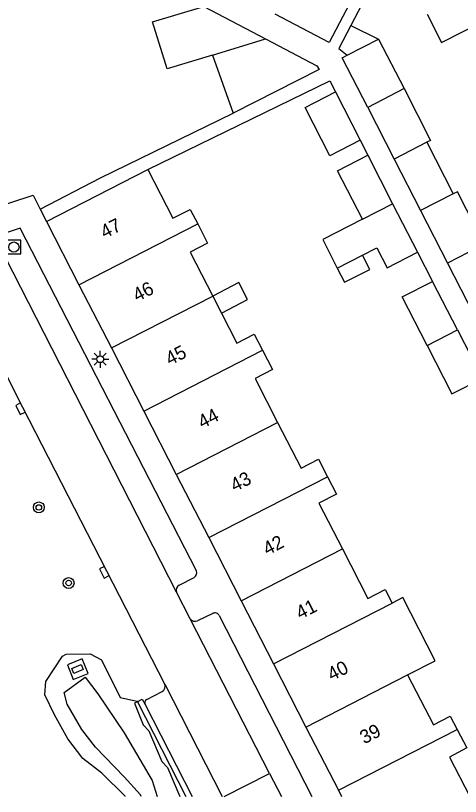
# Model space of a CAD drawing. Extents: x 132999 to 136000, y 398499 to 400501.
# Drawn here: x 133414.1 to 133446.8, y 398500 to 398557.3 of the extents above; entities that cross this region are included whole.
import ezdxf

# ---------------------------------------------------------------- set-up
doc = ezdxf.new("R2010")
doc.units = 0
for name, color, linetype in [('gg-afsc-erfafscheiding', 7, 'Continuous'), ('gg-anno-huisnummerreeks BGT', 7, 'Continuous'), ('gg-bbg-gedigitaliseerde bebouwing', 7, 'Continuous'), ('gg-bbg-gedigitaliseerde bijgebouw', 7, 'Continuous'), ('gg-bbg-hoofdgebouw', 7, 'Continuous'), ('gg-bbg-luifel en loopbrug', 7, 'Continuous'), ('gg-bbg-tussenscheiding', 7, 'Continuous'), ('gg-knt-verharding', 7, 'Continuous'), ('gg-knt-verharding nz', 7, 'Continuous'), ('gg-kntw-bovenkant insteek waterloop', 7, 'Continuous'), ('gg-kntw-waterlijn', 7, 'Continuous'), ('gt-grn-weggrens', 7, 'Continuous'), ('gt-symb-boom', 7, 'Continuous'), ('gt-symb-kolk', 7, 'Continuous'), ('gt-symb-kolk center center', 7, 'Continuous'), ('gt-symb-lichtmast', 7, 'Continuous'), ('gt-symb-rioolschacht', 7, 'Continuous')]:
    doc.layers.add(name, color=color, linetype=linetype)

# ---------------------------------------------------------------- blocks, each defined once
blk = doc.blocks.new('gt0-RS')
at = {"layer": 'gt-symb-rioolschacht'}
blk.add_lwpolyline([(-0.5, -0.5), (0.5, -0.5), (0.5, 0.5), (-0.5, 0.5)], close=True, dxfattribs=at)
blk.add_circle((0, 0), 0.375, dxfattribs=at)
blk = doc.blocks.new('gt0-KOLK')
at = {"layer": 'gt-symb-kolk'}
blk.add_lwpolyline([(0, 0), (0.375, 0), (0.375, 0.4), (-0.375, 0.4), (-0.375, 0), (0, 0)], dxfattribs=at)
blk = doc.blocks.new('gt0-BOOM')
at = {"layer": 'gt-symb-boom'}
for radius in [0.4, 0.2]:
    blk.add_circle((0, 0), radius, dxfattribs=at)
blk = doc.blocks.new('gt0-LMAST')
at = {"layer": 'gt-symb-lichtmast'}
for p, q in [((-0.005, 0.246), (-0.005, 0.621)), ((-0.182, 0.173), (-0.447, 0.438)), ((0.172, 0.173), (0.437, 0.438)), ((-0.255, -0.004), (-0.63, -0.004)), ((-0.182, -0.181), (-0.447, -0.446)), ((-0.005, -0.254), (-0.005, -0.629)), ((0.437, -0.446), (0.172, -0.181)), ((0.245, -0.004), (0.62, -0.004))]:
    blk.add_line(p, q, dxfattribs=at)
blk.add_circle((-0.005, -0.004), 0.25, dxfattribs=at)
blk = doc.blocks.new('gt0-KOLKCC')
at = {"layer": 'gt-symb-kolk center center'}
blk.add_lwpolyline([(-0.375, 0.2), (0.375, 0.2), (0.375, -0.2), (-0.375, -0.2)], close=True, dxfattribs=at)

msp = doc.modelspace()

# ---------------------------------------------------------------- linework, layer by layer
at = {"layer": 'gg-afsc-erfafscheiding'}
for p, q in [((133443.93, 398566.44), (133438.756, 398556.569)), ((133420.367, 398545.386), (133430.101, 398550.137)), ((133439.444, 398548.145), (133440.004, 398547.052)), ((133415.927, 398543.096), (133420.367, 398545.386)), ((133443.651, 398539.931), (133444.751, 398537.784))]:
    msp.add_line(p, q, dxfattribs=at)
for points in [[(133441.908, 398564.38), (133437.152, 398555.322), (133433.201, 398557.393)], [(133423.831, 398546.014), (133437.212, 398552.501), (133437.62, 398551.705)], [(133412.264, 398543.097), (133415.42, 398544.121), (133415.927, 398543.096)]]:
    msp.add_lwpolyline(points, dxfattribs=at)
at = {"layer": 'gg-bbg-gedigitaliseerde bebouwing'}
msp.add_line((133416.4, 398542.181), (133423.831, 398546.014), dxfattribs=at)
for points in [[(133444.364, 398557.399), (133445.426, 398555.328), (133451.732, 398558.56), (133452.532, 398557)], [(133423.831, 398546.014), (133425.677, 398542.421), (133426.955, 398543.078), (133427.504, 398542.011)], [(133427.504, 398542.011), (133428.233, 398540.593), (133426.954, 398539.935), (133428.608, 398536.72)], [(133429.251, 398535.469), (133430.385, 398533.266), (133431.658, 398533.921), (133432.268, 398532.736)], [(133432.268, 398532.736), (133432.998, 398531.317), (133431.719, 398530.659), (133433.373, 398527.445)], [(133433.373, 398527.445), (133435.098, 398524.093), (133436.377, 398524.746), (133437.032, 398523.462)], [(133437.032, 398523.462), (133437.691, 398522.18), (133436.412, 398521.523), (133438.135, 398518.169)], [(133438.135, 398518.169), (133440.006, 398514.527), (133441.284, 398515.184), (133441.797, 398514.187)], [(133442.925, 398508.908), (133444.958, 398509.953), (133442.577, 398514.588), (133441.797, 398514.187)], [(133442.925, 398508.908), (133444.837, 398505.256), (133446.056, 398505.894), (133446.568, 398504.916)], [(133446.568, 398504.916), (133447.28, 398503.555), (133445.991, 398502.881), (133447.497, 398500)]]:
    msp.add_lwpolyline(points, dxfattribs=at)
at = {"layer": 'gg-bbg-gedigitaliseerde bijgebouw'}
for p, q in [((133427.963, 398557.961), (133432.477, 398555.595)), ((133438.756, 398556.569), (133440.796, 398555.569)), ((133440.796, 398555.569), (133442.662, 398551.937)), ((133428.582, 398554.399), (133430.101, 398550.137)), ((133437.62, 398551.705), (133439.444, 398548.145)), ((133442.662, 398551.937), (133439.993, 398550.566)), ((133444.338, 398548.001), (133441.938, 398546.768)), ((133444.338, 398548.001), (133446.281, 398544.219)), ((133440.004, 398547.052), (133441.828, 398543.491)), ((133441.938, 398546.768), (133443.877, 398542.984)), ((133441.828, 398543.491), (133443.651, 398539.931)), ((133443.877, 398542.984), (133445.845, 398539.14)), ((133437.758, 398538.774), (133439.603, 398539.719)), ((133441.426, 398538.792), (133443.651, 398539.931)), ((133445.845, 398539.14), (133447.805, 398535.313)), ((133442.537, 398536.65), (133444.751, 398537.784)), ((133444.361, 398533.09), (133442.537, 398536.65)), ((133446.585, 398534.23), (133448.409, 398530.669))]:
    msp.add_line(p, q, dxfattribs=at)
for points in [[(133428.582, 398554.399), (133425.267, 398553.381), (133424.178, 398556.842), (133427.963, 398557.961)], [(133438.756, 398556.569), (133437.876, 398554.889), (133438.486, 398554.385)], [(133432.477, 398555.595), (133436.264, 398553.61), (133436.418, 398553.337), (133430.101, 398550.137)], [(133439.993, 398550.566), (133438.13, 398554.202), (133438.486, 398554.385)], [(133439.444, 398548.145), (133437.22, 398547.003), (133435.397, 398550.563), (133437.62, 398551.705)], [(133439.602, 398542.352), (133437.779, 398545.912), (133440.004, 398547.052)], [(133448.123, 398540.31), (133448.555, 398540.532), (133446.582, 398544.373), (133446.281, 398544.219)], [(133439.602, 398542.352), (133436.689, 398540.861), (133437.758, 398538.774)], [(133439.603, 398539.719), (133440.671, 398540.266), (133441.426, 398538.792)], [(133429.251, 398535.469), (133431.171, 398536.453), (133430.528, 398537.703), (133428.608, 398536.72)], [(133446.585, 398534.23), (133444.762, 398537.79), (133444.751, 398537.784)], [(133444.361, 398533.09), (133446.184, 398529.53), (133448.409, 398530.669)]]:
    msp.add_lwpolyline(points, dxfattribs=at)
at = {"layer": 'gg-bbg-hoofdgebouw'}
for p, q in [((133416.4, 398542.181), (133418.782, 398537.544)), ((133418.782, 398537.544), (133421.164, 398532.907)), ((133421.164, 398532.907), (133423.547, 398528.269)), ((133423.547, 398528.269), (133425.929, 398523.632)), ((133425.929, 398523.632), (133428.312, 398518.995)), ((133428.312, 398518.995), (133430.694, 398514.358)), ((133430.694, 398514.358), (133433.077, 398509.72)), ((133433.077, 398509.72), (133435.459, 398505.083)), ((133435.459, 398505.083), (133437.841, 398500.446)), ((133437.841, 398500.446), (133438.07, 398500))]:
    msp.add_line(p, q, dxfattribs=at)
at = {"layer": 'gg-bbg-luifel en loopbrug'}
msp.add_line((133439.993, 398550.566), (133441.938, 398546.768), dxfattribs=at)
for points in [[(133442.662, 398551.937), (133444.612, 398548.142), (133444.338, 398548.001)], [(133437.758, 398538.774), (133438.295, 398537.725), (133440.14, 398538.67), (133439.603, 398539.719)]]:
    msp.add_lwpolyline(points, dxfattribs=at)
at = {"layer": 'gg-bbg-tussenscheiding'}
for p, q in [((133428.582, 398554.399), (133432.477, 398555.595)), ((133438.486, 398554.385), (133440.796, 398555.569)), ((133446.281, 398544.219), (133443.877, 398542.984)), ((133439.602, 398542.352), (133441.828, 398543.491)), ((133418.782, 398537.544), (133427.504, 398542.011)), ((133448.123, 398540.31), (133445.845, 398539.14)), ((133421.164, 398532.907), (133428.608, 398536.72)), ((133428.608, 398536.72), (133429.251, 398535.469)), ((133444.361, 398533.09), (133446.585, 398534.23)), ((133423.547, 398528.269), (133432.268, 398532.736)), ((133425.929, 398523.632), (133433.373, 398527.445)), ((133428.312, 398518.995), (133437.032, 398523.462)), ((133430.694, 398514.358), (133438.135, 398518.169)), ((133433.077, 398509.72), (133441.797, 398514.187)), ((133435.459, 398505.083), (133442.925, 398508.908)), ((133437.841, 398500.446), (133446.568, 398504.916))]:
    msp.add_line(p, q, dxfattribs=at)
at = {"layer": 'gg-knt-verharding'}
for p, q in [((133426.134, 398515.497), (133427.241, 398516.057)), ((133426.951, 398513.038), (133425.952, 398514.984)), ((133428.629, 398513.433), (133427.485, 398512.879)), ((133429.079, 398513.269), (133435.879, 398500)), ((133423.763, 398507.108), (133424.894, 398507.7)), ((133423.074, 398506.946), (133423.116, 398506.968)), ((133423.074, 398506.946), (133426.637, 398500)), ((133423.639, 398506.741), (133427.097, 398500)), ((133423.503, 398505.256), (133423.918, 398504.818)), ((133423.918, 398504.818), (133424.867, 398502.565)), ((133424.867, 398502.565), (133425.298, 398502.109)), ((133425.298, 398502.109), (133426.19, 398500)), ((133429.452, 398500), (133432.785, 398501.683)), ((133432.785, 398501.683), (133433.651, 398500))]:
    msp.add_line(p, q, dxfattribs=at)
for points in [[(133427.406, 398516.56), (133414.476, 398541.702), (133412.579, 398541.097)], [(133425.094, 398508.236), (133414.662, 398528.539), (133412.752, 398532.293)], [(133417.932, 398509.652), (133418.368, 398508.572), (133419.45, 398509.019), (133419.014, 398510.098), (133417.932, 398509.652)], [(133423.074, 398506.946), (133422.875, 398506.84), (133423.503, 398505.256)], [(133423.116, 398506.968), (133423.438, 398507.132), (133423.639, 398506.741)]]:
    msp.add_lwpolyline(points, dxfattribs=at)
for centre, radius, start, end in [((133427.045, 398516.4), 0.395, 299.75581, 23.92192), ((133426.342, 398515.134), 0.418, 119.84547, 201.08762), ((133428.777, 398513.141), 0.328, 23.00272, 116.94931), ((133427.319, 398513.297), 0.45, 215.15443, 291.68347), ((133424.671, 398508.089), 0.448, 299.84988, 19.22558), ((133423.885, 398506.862), 0.274, 116.36438, 206.298)]:
    msp.add_arc(centre, radius, start, end, dxfattribs=at)
at = {"layer": 'gg-knt-verharding nz'}
for p, q in [((133425.952, 398514.984), (133412.579, 398541.097)), ((133432.785, 398501.683), (133426.951, 398513.038)), ((133425.094, 398508.236), (133429.307, 398500))]:
    msp.add_line(p, q, dxfattribs=at)
at = {"layer": 'gg-kntw-bovenkant insteek waterloop'}
msp.add_lwpolyline([(133422.178, 398500), (133422.171, 398500.011), (133420.473, 398501.704), (133419.063, 398502.77), (133417.968, 398504.215), (133416.99, 398505.987), (133416.268, 398507.455), (133416.353, 398508.436), (133417.564, 398510.278), (133417.854, 398510.43), (133419.599, 398510.462), (133420.451, 398510.03), (133421.799, 398507.262), (133423.053, 398506.996), (133423.116, 398506.968)], dxfattribs=at)
at = {"layer": 'gg-kntw-waterlijn'}
msp.add_lwpolyline([(133423.344, 398500), (133423.307, 398500.105), (133422.114, 398501.442), (133420, 398503.606), (133418.995, 398504.91), (133417.918, 398506.761), (133417.701, 398507.617), (133419.246, 398508.738), (133420.177, 398507.519), (133422.111, 398504.66), (133424.152, 398501.172), (133424.523, 398500)], dxfattribs=at)
at = {"layer": 'gt-grn-weggrens'}
msp.add_line((133415.927, 398543.096), (133416.4, 398542.181), dxfattribs=at)

# ---------------------------------------------------------------- block references
at = {"layer": 'gt-symb-boom'}
for p in [(133415.836, 398521.205), (133418.023, 398515.657)]:
    msp.add_blockref('gt0-BOOM', p, dxfattribs=at)
at = {"layer": 'gt-symb-kolk'}
for p, rotation in [((133414.662, 398528.539), 116.96205494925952), ((133420.824, 398516.538), 117.17858882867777)]:
    msp.add_blockref('gt0-KOLK', p, dxfattribs=dict(at, rotation=rotation))
at = {"layer": 'gt-symb-kolk center center', "rotation": 22.71112292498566}
msp.add_blockref('gt0-KOLKCC', (133418.672, 398509.355), dxfattribs=at)
at = {"layer": 'gt-symb-lichtmast'}
msp.add_blockref('gt0-LMAST', (133420.35, 398532.085), dxfattribs=at)
at = {"layer": 'gt-symb-rioolschacht'}
msp.add_blockref('gt0-RS', (133414.007, 398540.313), dxfattribs=at)

# ---------------------------------------------------------------- texts
at = {"layer": 'gg-anno-huisnummerreeks BGT'}
for s, p in [('47', (133420.676, 398540.909)), ('46', (133423.06, 398536.27)), ('45', (133425.46, 398531.599)), ('44', (133427.842, 398526.962)), ('43', (133430.225, 398522.325)), ('42', (133432.621, 398517.659)), ('41', (133435.039, 398512.955)), ('40', (133437.355, 398508.446)), ('39', (133439.737, 398503.809))]:
    msp.add_text(s, height=1, rotation=27.2, dxfattribs=at).set_placement(p)

doc.saveas('drawing.dxf')
